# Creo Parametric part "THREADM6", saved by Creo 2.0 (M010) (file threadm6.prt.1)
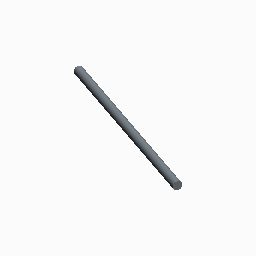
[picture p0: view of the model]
Units: Inch lbm Second (Pro/E Default); INCH, POUND, SECS

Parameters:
  CLASS = "2B"
  PLACEMENT = "EXTERNAL"

Other parameters: THREADS_PER_INCH

Created from: INLBS_PART_SOLID.PRT

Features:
  1. datum plane "RIGHT"
  2. datum plane "TOP"
  3. datum plane "FRONT"
  4. coordinate system
  5. sketch "Sketch 1"
  6. extrusion "Extrude 1", "Sketch 1"
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
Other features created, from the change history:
  sketch "Sketch 1"
  feature "Cosmetic Thread 1"

Surfaces: 5 plane, 2 cylinder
